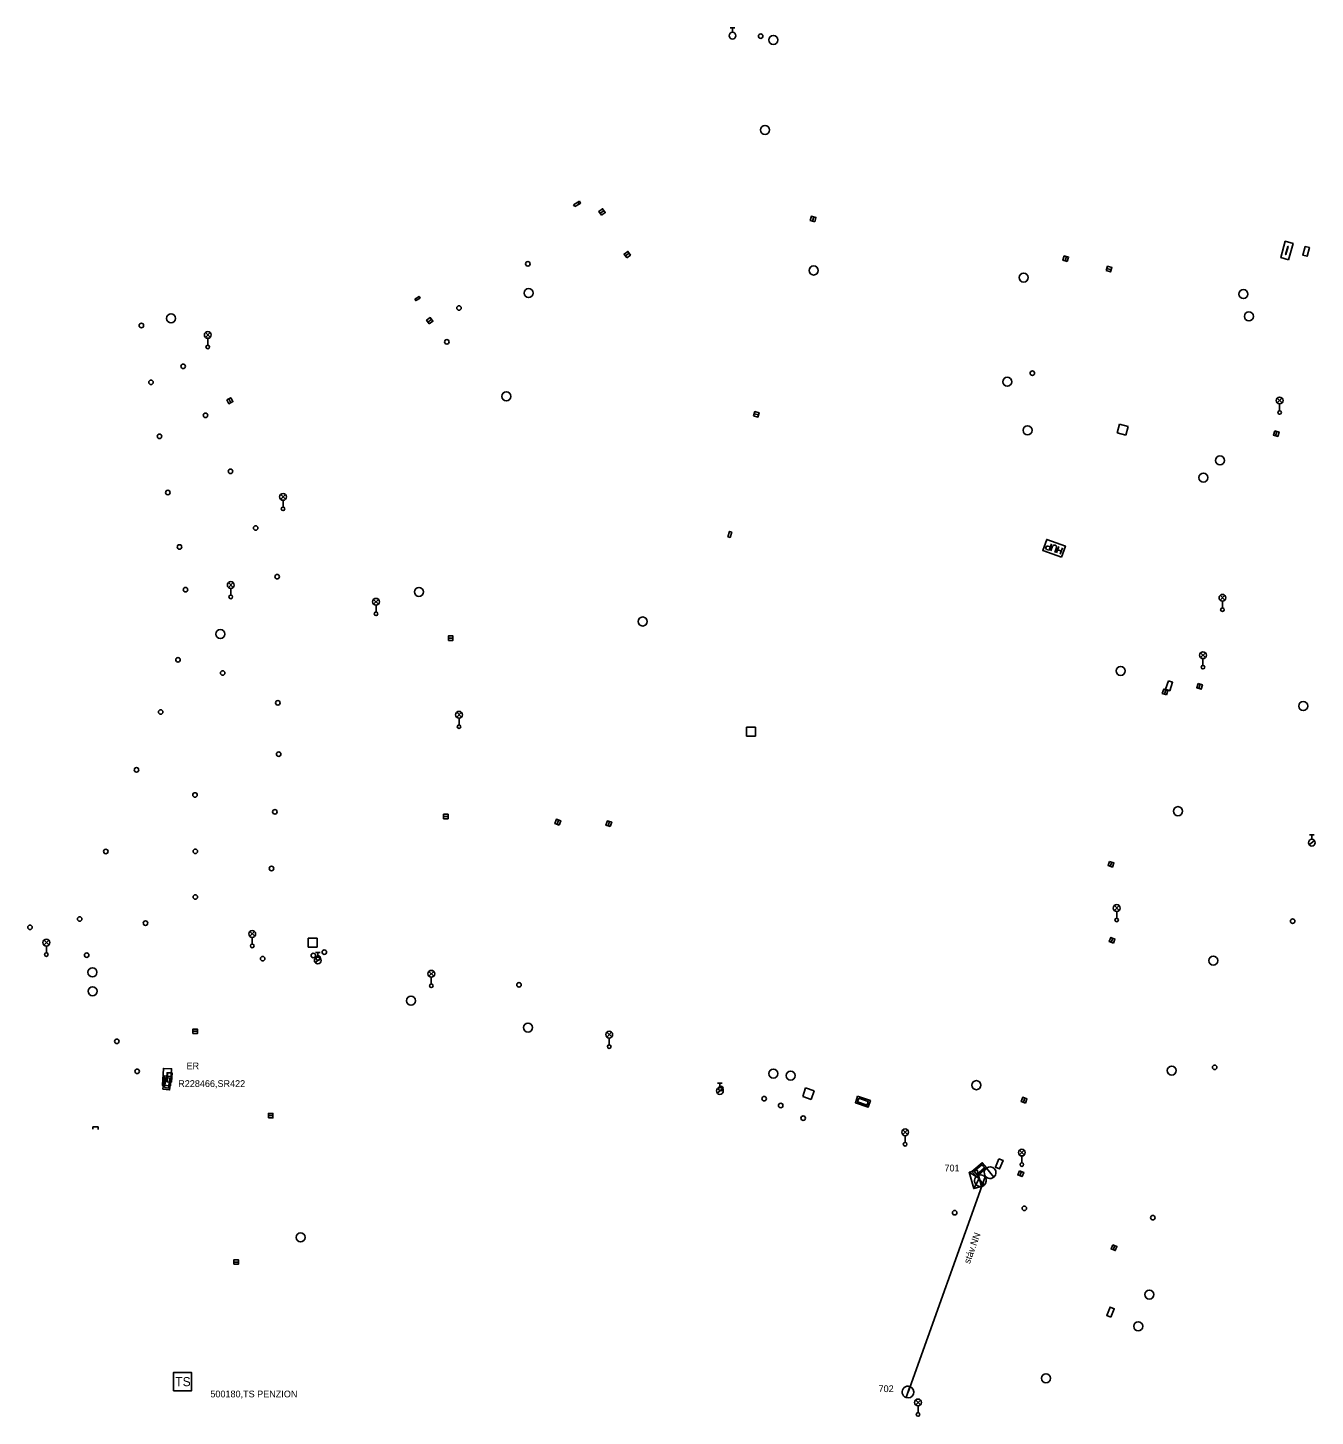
# Model space of a CAD drawing. Extents: x -584388 to -581645, y -1210859 to -1208922.
# Drawn here: x -582695.5 to -582552.9, y -1210006.3 to -1209852.5 of the extents above; entities that cross this region are included whole.
import ezdxf

# ---------------------------------------------------------------- set-up
doc = ezdxf.new("R2010")
doc.units = 0
for name, color, linetype in [('CIZÍ_NADZEM', 7, 'Continuous'), ('CIZÍ_PODZEM', 7, 'Continuous'), ('ELE_EON', 7, 'Continuous'), ('ELE_EON_POPIS', 7, 'Continuous')]:
    doc.layers.add(name, color=color, linetype=linetype)

msp = doc.modelspace()

# ---------------------------------------------------------------- linework, layer by layer
at = {"layer": 'CIZÍ_NADZEM'}
for p, q in [((-582617.68, -1209852.54), (-582617.18, -1209852.54)), ((-582617.43, -1209853.04), (-582617.43, -1209852.54)), ((-582632.08, -1209873.1), (-582631.68, -1209872.8)), ((-582608.58, -1209873.97), (-582608.44, -1209873.49)), ((-582629.29, -1209877.82), (-582628.89, -1209877.52)), ((-582580.59, -1209878.36), (-582580.45, -1209877.88)), ((-582575.95, -1209879.2), (-582575.47, -1209879.34)), ((-582651.18, -1209885.15), (-582650.78, -1209884.85)), ((-582675.83, -1209886.84), (-582675.31, -1209886.31)), ((-582675.3, -1209886.83), (-582675.83, -1209886.31)), ((-582675.57, -1209886.95), (-582675.57, -1209887.7)), ((-582673.25, -1209893.64), (-582673.01, -1209894.08)), ((-582557.08, -1209894.1), (-582556.56, -1209893.57)), ((-582556.55, -1209894.09), (-582557.08, -1209893.57)), ((-582556.82, -1209894.21), (-582556.82, -1209894.96)), ((-582615.02, -1209895.29), (-582614.54, -1209895.43)), ((-582574.55, -1209896.44), (-582574.83, -1209897.4)), ((-582574.83, -1209897.4), (-582573.87, -1209897.68)), ((-582573.59, -1209896.72), (-582574.55, -1209896.44)), ((-582573.87, -1209897.68), (-582573.59, -1209896.72)), ((-582557.12, -1209897.26), (-582557.26, -1209897.74)), ((-582667.49, -1209904.77), (-582666.97, -1209904.24)), ((-582666.96, -1209904.77), (-582667.49, -1209904.24)), ((-582667.23, -1209904.88), (-582667.23, -1209905.63)), ((-582673.28, -1209914.53), (-582672.76, -1209914)), ((-582672.75, -1209914.53), (-582673.28, -1209914)), ((-582673.02, -1209914.64), (-582673.02, -1209915.39)), ((-582657.19, -1209916.39), (-582656.67, -1209915.86)), ((-582656.66, -1209916.39), (-582657.19, -1209915.86)), ((-582563.42, -1209915.94), (-582562.9, -1209915.41)), ((-582562.89, -1209915.94), (-582563.42, -1209915.41)), ((-582656.93, -1209916.5), (-582656.93, -1209917.25)), ((-582563.16, -1209916.05), (-582563.16, -1209916.8)), ((-582648.9, -1209920.16), (-582648.4, -1209920.16)), ((-582565.57, -1209922.31), (-582565.05, -1209921.78)), ((-582565.04, -1209922.31), (-582565.57, -1209921.78)), ((-582565.31, -1209922.42), (-582565.31, -1209923.17)), ((-582565.61, -1209925.25), (-582565.77, -1209925.73)), ((-582569.59, -1209926.36), (-582569.43, -1209925.88)), ((-582647.99, -1209928.9), (-582647.47, -1209928.37)), ((-582647.46, -1209928.9), (-582647.99, -1209928.37)), ((-582647.73, -1209929.01), (-582647.73, -1209929.76)), ((-582614.88, -1209930.02), (-582615.88, -1209930.02)), ((-582615.88, -1209930.02), (-582615.88, -1209931.02)), ((-582615.88, -1209931.02), (-582614.88, -1209931.02)), ((-582614.88, -1209931.02), (-582614.88, -1209930.02)), ((-582649.44, -1209939.91), (-582648.94, -1209939.91)), ((-582636.86, -1209940.78), (-582636.7, -1209940.3)), ((-582631.22, -1209940.95), (-582631.06, -1209940.47)), ((-582553.5, -1209941.94), (-582553, -1209941.94)), ((-582553.25, -1209942.44), (-582553.25, -1209941.94)), ((-582553.54, -1209943.04), (-582552.95, -1209942.58)), ((-582575.42, -1209944.96), (-582575.58, -1209945.44)), ((-582575.13, -1209950.31), (-582574.61, -1209949.78)), ((-582574.6, -1209950.31), (-582575.13, -1209949.78)), ((-582574.87, -1209950.42), (-582574.87, -1209951.17)), ((-582670.9, -1209953.18), (-582670.38, -1209952.65)), ((-582670.37, -1209953.18), (-582670.9, -1209952.65)), ((-582693.71, -1209954.14), (-582693.19, -1209953.61)), ((-582693.18, -1209954.14), (-582693.71, -1209953.61)), ((-582693.45, -1209954.25), (-582693.45, -1209955)), ((-582670.64, -1209953.29), (-582670.64, -1209954.04)), ((-582663.46, -1209953.38), (-582664.46, -1209953.38)), ((-582664.46, -1209953.38), (-582664.46, -1209954.38)), ((-582664.46, -1209954.38), (-582663.46, -1209954.38)), ((-582663.46, -1209954.38), (-582663.46, -1209953.38)), ((-582575.47, -1209953.85), (-582575.29, -1209953.39)), ((-582663.67, -1209956.09), (-582663.08, -1209955.63)), ((-582663.63, -1209954.99), (-582663.13, -1209954.99)), ((-582663.38, -1209955.49), (-582663.38, -1209954.99)), ((-582651.06, -1209957.6), (-582650.54, -1209957.07)), ((-582650.53, -1209957.59), (-582651.06, -1209957.07)), ((-582650.8, -1209957.71), (-582650.8, -1209958.46)), ((-582677.22, -1209963.7), (-582676.72, -1209963.7)), ((-582631.35, -1209964.34), (-582630.83, -1209963.81)), ((-582630.82, -1209964.33), (-582631.35, -1209963.81)), ((-582631.09, -1209964.45), (-582631.09, -1209965.2)), ((-582619.08, -1209969.44), (-582618.58, -1209969.44)), ((-582618.83, -1209969.94), (-582618.83, -1209969.44)), ((-582619.12, -1209970.54), (-582618.53, -1209970.08)), ((-582609.35, -1209969.98), (-582609.66, -1209970.93)), ((-582609.66, -1209970.93), (-582608.71, -1209971.24)), ((-582608.4, -1209970.29), (-582609.35, -1209969.98)), ((-582608.71, -1209971.24), (-582608.4, -1209970.29)), ((-582585.21, -1209971.57), (-582585.05, -1209971.09)), ((-582668.85, -1209973.04), (-582668.35, -1209973.04)), ((-582598.57, -1209975.15), (-582598.05, -1209974.62)), ((-582598.04, -1209975.15), (-582598.57, -1209974.62)), ((-582598.31, -1209975.26), (-582598.31, -1209976.01)), ((-582585.64, -1209977.4), (-582585.12, -1209976.87)), ((-582585.11, -1209977.4), (-582585.64, -1209976.87)), ((-582585.38, -1209977.51), (-582585.38, -1209978.26)), ((-582585.4, -1209979.24), (-582585.6, -1209979.7)), ((-582575.07, -1209987.44), (-582575.27, -1209987.9)), ((-582672.67, -1209989.26), (-582672.17, -1209989.26)), ((-582597.14, -1210005.08), (-582596.62, -1210004.55)), ((-582596.61, -1210005.07), (-582597.14, -1210004.55)), ((-582596.88, -1210005.19), (-582596.88, -1210005.94))]:
    msp.add_line(p, q, dxfattribs=at)
for points in [[(-582634.57, -1209871.86), (-582635.04, -1209872.15)], [(-582634.91, -1209872.36), (-582635.04, -1209872.15)], [(-582634.91, -1209872.36), (-582634.44, -1209872.08)], [(-582634.57, -1209871.86), (-582634.4, -1209871.76)], [(-582634.44, -1209872.08), (-582634.57, -1209871.86)], [(-582634.44, -1209872.08), (-582634.27, -1209871.97), (-582634.4, -1209871.76)], [(-582652.05, -1209882.48), (-582652.15, -1209882.31), (-582652.62, -1209882.59)], [(-582652.05, -1209882.48), (-582652.52, -1209882.76), (-582652.62, -1209882.59)], [(-582617.94, -1209908.93), (-582617.76, -1209908.33), (-582617.52, -1209908.4)], [(-582617.94, -1209908.93), (-582617.7, -1209909), (-582617.52, -1209908.4)], [(-582581, -1209911.2), (-582583.07, -1209910.46), (-582582.62, -1209909.22), (-582580.56, -1209909.96), (-582581, -1209911.2)], [(-582582.1, -1209909.7), (-582582.36, -1209910.42)], [(-582581.74, -1209910.65), (-582581.55, -1209910.13), (-582581.54, -1209910.02), (-582581.58, -1209909.92), (-582581.66, -1209909.86), (-582581.72, -1209909.84), (-582581.82, -1209909.84), (-582581.9, -1209909.89), (-582581.97, -1209909.98), (-582582.15, -1209910.5)], [(-582582.36, -1209910.42), (-582582.63, -1209910.33), (-582582.7, -1209910.26), (-582582.72, -1209910.22), (-582582.72, -1209910.14), (-582582.69, -1209910.03), (-582582.63, -1209909.98), (-582582.59, -1209909.95), (-582582.49, -1209909.95), (-582582.22, -1209910.05)], [(-582581.27, -1209910), (-582581.53, -1209910.72)], [(-582580.99, -1209910.53), (-582581.41, -1209910.38)], [(-582581.12, -1209910.87), (-582580.86, -1209910.15)]]:
    msp.add_lwpolyline(points, dxfattribs=at)
for points in [[(-582631.94, -1209873.3), (-582631.53, -1209873.01), (-582631.82, -1209872.6), (-582632.23, -1209872.89)], [(-582608.33, -1209874.04), (-582608.2, -1209873.56), (-582608.69, -1209873.42), (-582608.82, -1209873.9)], [(-582629.15, -1209878.02), (-582628.74, -1209877.73), (-582629.03, -1209877.32), (-582629.44, -1209877.61)], [(-582554, -1209876.76), (-582554.26, -1209877.73), (-582553.78, -1209877.86), (-582553.52, -1209876.89)], [(-582580.35, -1209878.43), (-582580.21, -1209877.95), (-582580.69, -1209877.81), (-582580.83, -1209878.29)], [(-582576.02, -1209879.44), (-582575.54, -1209879.58), (-582575.4, -1209879.1), (-582575.88, -1209878.96)], [(-582651.04, -1209885.35), (-582650.63, -1209885.06), (-582650.92, -1209884.65), (-582651.33, -1209884.94)], [(-582673.47, -1209893.76), (-582673.23, -1209894.2), (-582672.79, -1209893.96), (-582673.03, -1209893.52)], [(-582615.09, -1209895.54), (-582614.61, -1209895.67), (-582614.47, -1209895.18), (-582614.95, -1209895.05)], [(-582557.36, -1209897.19), (-582557.5, -1209897.67), (-582557.02, -1209897.81), (-582556.88, -1209897.33)], [(-582648.9, -1209920.41), (-582648.4, -1209920.41), (-582648.4, -1209919.91), (-582648.9, -1209919.91)], [(-582569.14, -1209924.88), (-582569.47, -1209925.82), (-582569, -1209925.98), (-582568.67, -1209925.04)], [(-582565.85, -1209925.18), (-582566.01, -1209925.65), (-582565.53, -1209925.81), (-582565.38, -1209925.33)], [(-582569.36, -1209926.44), (-582569.19, -1209925.97), (-582569.66, -1209925.8), (-582569.83, -1209926.27)], [(-582649.44, -1209940.16), (-582648.94, -1209940.16), (-582648.94, -1209939.66), (-582649.44, -1209939.66)], [(-582636.62, -1209940.86), (-582636.46, -1209940.38), (-582636.94, -1209940.22), (-582637.1, -1209940.7)], [(-582630.98, -1209941.03), (-582630.82, -1209940.55), (-582631.3, -1209940.39), (-582631.46, -1209940.87)], [(-582575.65, -1209944.88), (-582575.82, -1209945.35), (-582575.35, -1209945.52), (-582575.18, -1209945.05)], [(-582575.24, -1209953.94), (-582575.06, -1209953.48), (-582575.52, -1209953.3), (-582575.7, -1209953.76)], [(-582677.22, -1209963.95), (-582676.72, -1209963.95), (-582676.72, -1209963.45), (-582677.22, -1209963.45)], [(-582679.58, -1209969.32), (-582679.52, -1209968.32), (-582680.02, -1209968.3), (-582680.08, -1209969.3)], [(-582584.98, -1209971.65), (-582584.81, -1209971.18), (-582585.28, -1209971.01), (-582585.45, -1209971.48)], [(-582668.85, -1209973.29), (-582668.35, -1209973.29), (-582668.35, -1209972.79), (-582668.85, -1209972.79)], [(-582587.92, -1209977.82), (-582588.3, -1209978.75), (-582587.84, -1209978.94), (-582587.46, -1209978.01)], [(-582585.64, -1209979.14), (-582585.83, -1209979.61), (-582585.36, -1209979.8), (-582585.17, -1209979.34)], [(-582575.31, -1209987.34), (-582575.5, -1209987.81), (-582575.03, -1209988), (-582574.84, -1209987.53)], [(-582672.67, -1209989.51), (-582672.17, -1209989.51), (-582672.17, -1209989.01), (-582672.67, -1209989.01)], [(-582575.52, -1209995.37), (-582575.14, -1209994.44), (-582575.6, -1209994.25), (-582575.98, -1209995.18)]]:
    msp.add_lwpolyline(points, close=True, dxfattribs=at)
for centre, radius in [((-582617.43, -1209853.42), 0.375), ((-582614.31, -1209853.47), 0.25), ((-582612.91, -1209853.89), 0.5), ((-582613.83, -1209863.86), 0.5), ((-582640.11, -1209878.69), 0.25), ((-582608.45, -1209879.43), 0.5), ((-582585.18, -1209880.21), 0.5), ((-582640.03, -1209881.93), 0.5), ((-582560.83, -1209882.05), 0.5), ((-582647.73, -1209883.59), 0.25), ((-582682.92, -1209885.52), 0.25), ((-582679.63, -1209884.73), 0.5), ((-582560.23, -1209884.51), 0.5), ((-582675.57, -1209886.57), 0.375), ((-582675.57, -1209887.9), 0.2), ((-582649.08, -1209887.34), 0.25), ((-582678.29, -1209890.05), 0.25), ((-582587, -1209891.76), 0.5), ((-582584.21, -1209890.81), 0.25), ((-582681.85, -1209891.82), 0.25), ((-582642.49, -1209893.37), 0.5), ((-582556.82, -1209893.83), 0.375), ((-582675.82, -1209895.48), 0.25), ((-582556.82, -1209895.16), 0.2), ((-582680.92, -1209897.8), 0.25), ((-582584.75, -1209897.13), 0.5), ((-582563.43, -1209900.47), 0.5), ((-582673.04, -1209901.68), 0.25), ((-582565.26, -1209902.37), 0.5), ((-582679.99, -1209904.03), 0.25), ((-582667.23, -1209904.51), 0.375), ((-582667.23, -1209905.83), 0.2), ((-582670.26, -1209907.95), 0.25), ((-582678.7, -1209910.05), 0.25), ((-582673.02, -1209914.27), 0.375), ((-582667.88, -1209913.34), 0.25), ((-582678.04, -1209914.78), 0.25), ((-582673.02, -1209915.59), 0.2), ((-582656.93, -1209916.12), 0.375), ((-582652.18, -1209915.03), 0.5), ((-582563.16, -1209915.68), 0.375), ((-582656.93, -1209917.45), 0.2), ((-582563.16, -1209917), 0.2), ((-582627.38, -1209918.31), 0.5), ((-582674.17, -1209919.7), 0.5), ((-582565.31, -1209922.05), 0.375), ((-582678.86, -1209922.55), 0.25), ((-582574.44, -1209923.78), 0.5), ((-582565.31, -1209923.37), 0.2), ((-582673.92, -1209924.02), 0.25), ((-582680.78, -1209928.34), 0.25), ((-582667.81, -1209927.32), 0.25), ((-582647.73, -1209928.64), 0.375), ((-582554.21, -1209927.68), 0.5), ((-582647.73, -1209929.96), 0.2), ((-582667.71, -1209933), 0.25), ((-582683.46, -1209934.75), 0.25), ((-582676.98, -1209937.52), 0.25), ((-582568.08, -1209939.32), 0.5), ((-582668.13, -1209939.39), 0.25), ((-582686.87, -1209943.78), 0.25), ((-582676.94, -1209943.77), 0.25), ((-582553.25, -1209942.81), 0.375), ((-582668.51, -1209945.67), 0.25), ((-582676.94, -1209948.82), 0.25), ((-582574.87, -1209950.05), 0.375), ((-582689.76, -1209951.27), 0.25), ((-582574.87, -1209951.37), 0.2), ((-582555.38, -1209951.5), 0.25), ((-582695.26, -1209952.18), 0.25), ((-582682.47, -1209951.72), 0.25), ((-582670.64, -1209952.92), 0.375), ((-582693.45, -1209953.88), 0.375), ((-582670.64, -1209954.24), 0.2), ((-582693.45, -1209955.2), 0.2), ((-582688.98, -1209955.26), 0.25), ((-582669.48, -1209955.65), 0.25), ((-582663.88, -1209955.31), 0.25), ((-582663.38, -1209955.86), 0.375), ((-582663.34, -1209955.58), 0.25), ((-582662.66, -1209954.93), 0.25), ((-582564.18, -1209955.87), 0.5), ((-582688.34, -1209957.17), 0.5), ((-582650.8, -1209957.33), 0.375), ((-582688.33, -1209959.26), 0.5), ((-582650.8, -1209958.66), 0.2), ((-582641.09, -1209958.56), 0.25), ((-582653.06, -1209960.31), 0.5), ((-582640.09, -1209963.29), 0.5), ((-582631.09, -1209964.07), 0.375), ((-582685.64, -1209964.82), 0.25), ((-582631.09, -1209965.4), 0.2), ((-582683.38, -1209968.13), 0.25), ((-582612.91, -1209968.39), 0.5), ((-582611, -1209968.61), 0.5), ((-582568.77, -1209968.05), 0.5), ((-582564.02, -1209967.69), 0.25), ((-582618.72, -1209970.04), 0.25), ((-582590.42, -1209969.67), 0.5), ((-582618.83, -1209970.31), 0.375), ((-582613.92, -1209971.17), 0.25), ((-582612.09, -1209971.93), 0.25), ((-582609.6, -1209973.32), 0.25), ((-582598.31, -1209974.89), 0.375), ((-582598.31, -1209976.21), 0.2), ((-582585.38, -1209977.14), 0.375), ((-582585.38, -1209978.46), 0.2), ((-582592.82, -1209983.8), 0.25), ((-582585.1, -1209983.31), 0.25), ((-582570.87, -1209984.34), 0.25), ((-582665.29, -1209986.53), 0.5), ((-582571.25, -1209992.86), 0.5), ((-582572.49, -1209996.38), 0.5), ((-582582.71, -1210002.14), 0.5), ((-582596.88, -1210004.81), 0.375), ((-582596.88, -1210006.14), 0.2)]:
    msp.add_circle(centre, radius, dxfattribs=at)
at = {"layer": 'CIZÍ_PODZEM'}
for points in [[(-582688.31, -1209974.56), (-582688.3, -1209974.3), (-582687.71, -1209974.29)], [(-582687.71, -1209974.57), (-582687.71, -1209974.29)]]:
    msp.add_lwpolyline(points, dxfattribs=at)
at = {"layer": 'ELE_EON'}
for p, q in [((-582588.48, -1209979.86), (-582589.31, -1209978.86)), ((-582589.55, -1209980.76), (-582590.38, -1209979.76)), ((-582597.77, -1210003.05), (-582598.21, -1210004.27))]:
    msp.add_line(p, q, dxfattribs=at)
for points in [[(-582555.83, -1209878.24), (-582555.33, -1209876.44), (-582556.19, -1209876.19), (-582556.7, -1209878)], [(-582556.12, -1209877.67), (-582555.87, -1209876.77), (-582555.9, -1209876.76), (-582556.16, -1209877.66)], [(-582679.7, -1209969.74), (-582679.58, -1209967.86), (-582680.48, -1209967.81), (-582680.6, -1209969.68)], [(-582680.1, -1209969.24), (-582680.04, -1209968.31), (-582680.08, -1209968.3), (-582680.14, -1209969.24)], [(-582680.54, -1209970.11), (-582680.35, -1209968.62), (-582679.6, -1209968.72), (-582679.8, -1209970.2)], [(-582680.36, -1209969.93), (-582680.23, -1209968.84), (-582679.78, -1209968.9), (-582679.92, -1209969.99)], [(-582603.57, -1209970.9), (-582602.15, -1209971.38), (-582602.39, -1209972.09), (-582603.81, -1209971.61)], [(-582603.43, -1209971.1), (-582602.39, -1209971.46), (-582602.53, -1209971.89), (-582603.57, -1209971.53)], [(-582589.84, -1209980.89), (-582590.34, -1209979.09), (-582591.2, -1209979.32), (-582590.71, -1209981.13)], [(-582590.91, -1209979.23), (-582589.76, -1209978.26), (-582589.28, -1209978.83), (-582590.42, -1209979.8)], [(-582590.66, -1209979.21), (-582589.82, -1209978.5), (-582589.53, -1209978.84), (-582590.37, -1209979.56)], [(-582679.37, -1210003.51), (-582677.37, -1210003.51), (-582677.37, -1210001.51), (-582679.37, -1210001.51)]]:
    msp.add_lwpolyline(points, close=True, dxfattribs=at)
for points in [[(-582589.43, -1209979.81), (-582597.99, -1210003.66)], [(-582590.71, -1209981.13), (-582590.09, -1209979.99), (-582591.2, -1209979.32)]]:
    msp.add_lwpolyline(points, dxfattribs=at)
for centre, start, end in [((-582588.89, -1209979.36), 129.9869, 309.9869), ((-582588.89, -1209979.36), 309.9869, 129.9869), ((-582589.97, -1209980.26), 129.9869, 309.9869), ((-582589.97, -1209980.26), 309.9869, 129.9869), ((-582597.99, -1210003.66), 70.2564, 250.2564), ((-582597.99, -1210003.66), 250.2564, 70.2564)]:
    msp.add_arc(centre, 0.65, start, end, dxfattribs=at)

# ---------------------------------------------------------------- texts
msp.add_text('TS', height=1, dxfattribs=at).set_placement((-582679.17, -1210003.01))
at = {"layer": 'ELE_EON_POPIS'}
for s, p in [('ER', (-582677.92, -1209967.91)), ('R228466,SR422', (-582678.84, -1209969.87)), ('701', (-582593.95, -1209979.23)), ('500180,TS PENZION', (-582675.28, -1210004.25)), ('702', (-582601.25, -1210003.67))]:
    msp.add_text(s, height=0.75, dxfattribs=at).set_placement(p)
msp.add_text('stáv.NN', height=0.75, rotation=70.2564, dxfattribs=at).set_placement((-582591.14, -1209989.51))

doc.saveas('drawing.dxf')
